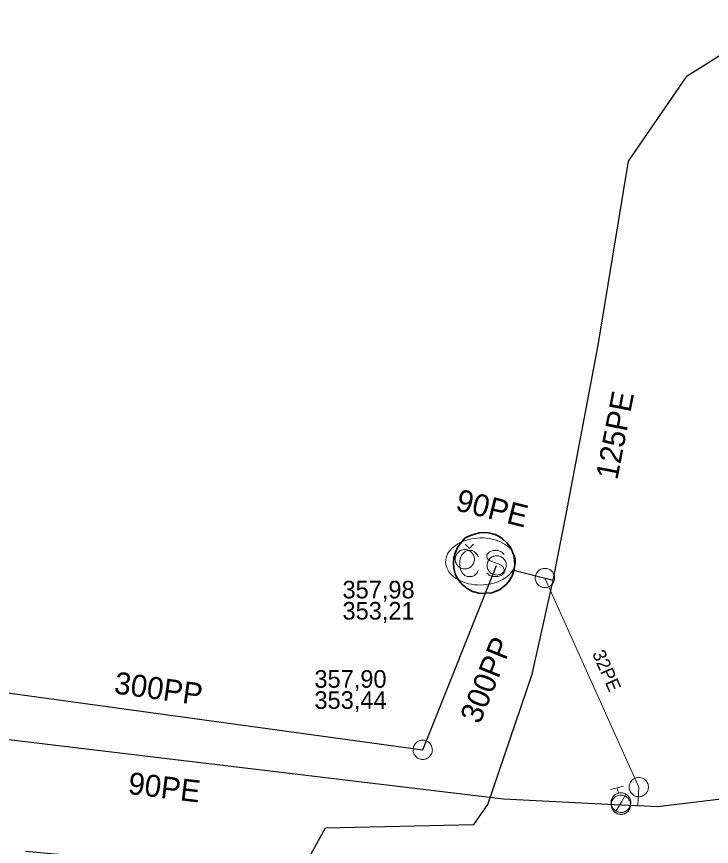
# Model space of a CAD drawing. Extents: x -741806 to -738704, y -1059275 to -1055387.
# Drawn here: x -740753.77 to -740722.25, y -1057687.05 to -1057649.38 of the extents above; entities that cross this region are included whole.
import ezdxf

# ---------------------------------------------------------------- set-up
doc = ezdxf.new("R2010")
doc.units = 0
doc.header["$LTSCALE"] = 0.4
for name, color, linetype, lineweight in [('11', 7, 'Continuous', 13), ('2', 7, 'Continuous', 25), ('21', 7, 'Continuous', 13), ('3', 7, 'Continuous', 13), ('45', 7, 'Continuous', 35), ('50', 7, 'Continuous', 13), ('51', 7, 'Continuous', 13), ('52', 7, 'Continuous', 25), ('6', 7, 'Continuous', 13)]:
    doc.layers.add(name, color=color, linetype=linetype, lineweight=lineweight)
for name, color, linetype in [('5', 7, 'Continuous'), ('53', 7, 'Continuous'), ('54', 7, 'Continuous')]:
    doc.layers.add(name, color=color, linetype=linetype)

msp = doc.modelspace()

# ---------------------------------------------------------------- linework, layer by layer
at = {"layer": '11'}
for q in [(-740733.428, -1057673.337), (-740733.036, -1057673.337)]:
    msp.add_line((-740733.232, -1057673.528), q, dxfattribs=at)
msp.add_lwpolyline([(-740731.135, -1057674.086), (-740731.143, -1057673.993), (-740731.163, -1057673.901), (-740731.194, -1057673.811), (-740731.237, -1057673.723), (-740731.292, -1057673.639), (-740731.357, -1057673.557), (-740731.432, -1057673.48), (-740731.517, -1057673.408), (-740731.612, -1057673.341), (-740731.714, -1057673.28), (-740731.824, -1057673.226), (-740731.941, -1057673.178), (-740732.064, -1057673.137), (-740732.192, -1057673.103), (-740732.324, -1057673.077), (-740732.459, -1057673.059), (-740732.596, -1057673.049), (-740732.734, -1057673.048), (-740732.872, -1057673.054), (-740733.009, -1057673.068), (-740733.143, -1057673.09), (-740733.274, -1057673.12), (-740733.402, -1057673.157), (-740733.524, -1057673.202), (-740733.64, -1057673.253), (-740733.749, -1057673.311), (-740733.85, -1057673.375), (-740733.943, -1057673.445), (-740734.027, -1057673.52), (-740734.1, -1057673.599), (-740734.164, -1057673.682), (-740734.216, -1057673.769), (-740734.257, -1057673.858), (-740734.287, -1057673.949), (-740734.305, -1057674.041), (-740734.311, -1057674.134), (-740734.305, -1057674.227), (-740734.286, -1057674.318), (-740734.257, -1057674.409), (-740734.215, -1057674.497), (-740734.162, -1057674.582), (-740734.099, -1057674.664), (-740734.025, -1057674.742), (-740733.941, -1057674.814), (-740733.848, -1057674.882), (-740733.746, -1057674.944), (-740733.637, -1057674.999), (-740733.521, -1057675.048), (-740733.399, -1057675.09), (-740733.271, -1057675.125), (-740733.14, -1057675.152), (-740733.005, -1057675.171), (-740732.868, -1057675.182), (-740732.731, -1057675.185), (-740732.593, -1057675.18), (-740732.456, -1057675.167), (-740732.321, -1057675.146), (-740732.189, -1057675.117), (-740732.061, -1057675.08), (-740731.938, -1057675.037), (-740731.822, -1057674.986), (-740731.711, -1057674.929), (-740731.609, -1057674.866), (-740731.515, -1057674.797), (-740731.43, -1057674.723), (-740731.355, -1057674.644), (-740731.29, -1057674.561), (-740731.236, -1057674.475), (-740731.193, -1057674.387), (-740731.162, -1057674.296), (-740731.143, -1057674.204), (-740731.135, -1057674.111)], close=True, dxfattribs=at)
for points in [[(-740732.828, -1057673.906), (-740732.884, -1057673.794), (-740732.996, -1057673.682), (-740733.108, -1057673.626), (-740733.33, -1057673.626), (-740733.439, -1057673.682), (-740733.551, -1057673.794), (-740733.615, -1057673.906), (-740733.671, -1057674.068), (-740733.671, -1057674.357), (-740733.615, -1057674.522), (-740733.551, -1057674.634), (-740733.439, -1057674.749), (-740733.33, -1057674.799), (-740733.108, -1057674.799), (-740732.996, -1057674.749), (-740732.884, -1057674.634), (-740732.828, -1057674.522)], [(-740731.655, -1057673.794), (-740731.767, -1057673.682), (-740731.932, -1057673.626), (-740732.156, -1057673.626), (-740732.324, -1057673.682), (-740732.442, -1057673.794), (-740732.442, -1057673.906), (-740732.389, -1057674.015), (-740732.324, -1057674.068), (-740732.21, -1057674.124), (-740731.876, -1057674.236), (-740731.767, -1057674.301), (-740731.711, -1057674.357), (-740731.655, -1057674.469), (-740731.655, -1057674.634), (-740731.767, -1057674.749), (-740731.932, -1057674.799), (-740732.156, -1057674.799), (-740732.324, -1057674.749), (-740732.442, -1057674.634)]]:
    msp.add_lwpolyline(points, dxfattribs=at)
at = {"layer": '2'}
for p, q in [((-740735.349, -1057682.666), (-740731.993, -1057674.294)), ((-740731.17, -1057674.524), (-740729.436, -1057674.959))]:
    msp.add_line(p, q, dxfattribs=at)
for points in [[(-740723.35, -1057652.071), (-740715.67, -1057647.25), (-740702.59, -1057629.575)], [(-740765.321, -1057634.66), (-740765.339, -1057637.145), (-740765.221, -1057649.531), (-740765.019, -1057662.11), (-740765.083, -1057671.477), (-740757.826, -1057679.575), (-740735.349, -1057682.666)], [(-740753.366, -1057687.272), (-740740.964, -1057688.405), (-740739.761, -1057686.21), (-740733.024, -1057686.05), (-740732.395, -1057685.151), (-740730.385, -1057679.235), (-740729.436, -1057674.959), (-740728.829, -1057671.892), (-740727.385, -1057664.297), (-740726.006, -1057655.95), (-740723.35, -1057652.071)]]:
    msp.add_lwpolyline(points, dxfattribs=at)
at = {"layer": '21'}
msp.add_lwpolyline([(-740725.581, -1057685.195), (-740725.546, -1057684.358), (-740729.804, -1057674.867)], dxfattribs=at)
at = {"layer": '3'}
for points in [[(-740732.999, -1057674.015), (-740733.002, -1057673.97), (-740733.009, -1057673.925), (-740733.021, -1057673.88), (-740733.037, -1057673.838), (-740733.058, -1057673.797), (-740733.083, -1057673.758), (-740733.112, -1057673.723), (-740733.144, -1057673.69), (-740733.18, -1057673.662), (-740733.218, -1057673.637), (-740733.259, -1057673.616), (-740733.302, -1057673.599), (-740733.346, -1057673.588), (-740733.391, -1057673.58), (-740733.437, -1057673.578), (-740733.483, -1057673.58), (-740733.528, -1057673.588), (-740733.572, -1057673.599), (-740733.615, -1057673.616), (-740733.656, -1057673.637), (-740733.694, -1057673.662), (-740733.729, -1057673.69), (-740733.762, -1057673.723), (-740733.791, -1057673.758), (-740733.816, -1057673.797), (-740733.836, -1057673.838), (-740733.853, -1057673.88), (-740733.865, -1057673.925), (-740733.872, -1057673.97), (-740733.874, -1057674.016), (-740733.872, -1057674.061), (-740733.865, -1057674.106), (-740733.853, -1057674.151), (-740733.836, -1057674.194), (-740733.816, -1057674.234), (-740733.791, -1057674.273), (-740733.762, -1057674.308), (-740733.729, -1057674.341), (-740733.694, -1057674.369), (-740733.656, -1057674.394), (-740733.615, -1057674.415), (-740733.572, -1057674.432), (-740733.528, -1057674.444), (-740733.483, -1057674.451), (-740733.437, -1057674.453), (-740733.391, -1057674.451), (-740733.346, -1057674.444), (-740733.302, -1057674.432), (-740733.259, -1057674.415), (-740733.218, -1057674.394), (-740733.18, -1057674.369), (-740733.144, -1057674.341), (-740733.112, -1057674.308), (-740733.083, -1057674.273), (-740733.058, -1057674.234), (-740733.037, -1057674.193), (-740733.021, -1057674.151), (-740733.009, -1057674.106), (-740733.002, -1057674.061), (-740732.999, -1057674.016)], [(-740731.829, -1057673.887), (-740731.872, -1057673.873), (-740731.916, -1057673.863), (-740731.963, -1057673.857), (-740732.007, -1057673.857), (-740732.053, -1057673.861), (-740732.099, -1057673.869), (-740732.142, -1057673.883), (-740732.185, -1057673.901), (-740732.224, -1057673.924), (-740732.261, -1057673.95), (-740732.296, -1057673.98), (-740732.328, -1057674.014), (-740732.355, -1057674.05), (-740732.379, -1057674.089), (-740732.398, -1057674.131), (-740732.413, -1057674.175), (-740732.422, -1057674.219), (-740732.428, -1057674.264), (-740732.429, -1057674.31), (-740732.424, -1057674.356), (-740732.415, -1057674.401), (-740732.402, -1057674.444), (-740732.384, -1057674.487), (-740732.362, -1057674.527), (-740732.335, -1057674.564), (-740732.305, -1057674.598), (-740732.272, -1057674.63), (-740732.235, -1057674.657), (-740732.196, -1057674.681), (-740732.154, -1057674.7), (-740732.111, -1057674.715), (-740732.067, -1057674.725), (-740732.021, -1057674.73), (-740731.974, -1057674.731), (-740731.93, -1057674.727), (-740731.884, -1057674.718), (-740731.841, -1057674.704), (-740731.798, -1057674.686), (-740731.759, -1057674.664), (-740731.722, -1057674.638), (-740731.687, -1057674.608), (-740731.655, -1057674.574), (-740731.628, -1057674.538), (-740731.604, -1057674.499), (-740731.585, -1057674.457), (-740731.57, -1057674.413), (-740731.56, -1057674.369), (-740731.555, -1057674.324), (-740731.555, -1057674.277), (-740731.559, -1057674.231), (-740731.568, -1057674.187), (-740731.58, -1057674.143), (-740731.599, -1057674.101), (-740731.621, -1057674.061), (-740731.648, -1057674.023), (-740731.678, -1057673.989), (-740731.711, -1057673.958), (-740731.748, -1057673.93), (-740731.787, -1057673.907), (-740731.828, -1057673.888)], [(-740734.915, -1057682.726), (-740734.911, -1057682.681), (-740734.912, -1057682.635), (-740734.918, -1057682.589), (-740734.928, -1057682.545), (-740734.943, -1057682.502), (-740734.963, -1057682.46), (-740734.987, -1057682.421), (-740735.014, -1057682.384), (-740735.046, -1057682.351), (-740735.08, -1057682.321), (-740735.118, -1057682.295), (-740735.158, -1057682.272), (-740735.2, -1057682.255), (-740735.244, -1057682.241), (-740735.289, -1057682.233), (-740735.335, -1057682.229), (-740735.381, -1057682.231), (-740735.426, -1057682.235), (-740735.471, -1057682.246), (-740735.514, -1057682.262), (-740735.555, -1057682.281), (-740735.594, -1057682.304), (-740735.631, -1057682.332), (-740735.664, -1057682.363), (-740735.694, -1057682.398), (-740735.72, -1057682.436), (-740735.742, -1057682.476), (-740735.76, -1057682.519), (-740735.773, -1057682.562), (-740735.782, -1057682.607), (-740735.786, -1057682.652), (-740735.785, -1057682.698), (-740735.779, -1057682.744), (-740735.768, -1057682.789), (-740735.754, -1057682.831), (-740735.734, -1057682.873), (-740735.71, -1057682.912), (-740735.682, -1057682.949), (-740735.651, -1057682.982), (-740735.617, -1057683.012), (-740735.579, -1057683.038), (-740735.539, -1057683.061), (-740735.497, -1057683.079), (-740735.454, -1057683.092), (-740735.408, -1057683.1), (-740735.362, -1057683.104), (-740735.317, -1057683.103), (-740735.272, -1057683.097), (-740735.227, -1057683.087), (-740735.183, -1057683.071), (-740735.142, -1057683.052), (-740735.103, -1057683.029), (-740735.067, -1057683.001), (-740735.033, -1057682.97), (-740735.003, -1057682.935), (-740734.977, -1057682.897), (-740734.955, -1057682.857), (-740734.937, -1057682.814), (-740734.924, -1057682.771), (-740734.915, -1057682.727)]]:
    msp.add_lwpolyline(points, dxfattribs=at)
at = {"layer": '45'}
msp.add_lwpolyline([(-740732.061, -1057672.894), (-740732.367, -1057672.814), (-740732.586, -1057672.8), (-740732.78, -1057672.817), (-740733.175, -1057672.941), (-740733.416, -1057673.037), (-740733.584, -1057673.244), (-740733.747, -1057673.456), (-740733.867, -1057673.695), (-740733.934, -1057673.929), (-740733.958, -1057674.171), (-740733.934, -1057674.438), (-740733.869, -1057674.673), (-740733.81, -1057674.807), (-740733.668, -1057675.034), (-740733.556, -1057675.163), (-740733.331, -1057675.348), (-740733.094, -1057675.474), (-740732.741, -1057675.568), (-740732.496, -1057675.55), (-740732.209, -1057675.535), (-740731.871, -1057675.398), (-740731.562, -1057675.161), (-740731.408, -1057674.973), (-740731.288, -1057674.761), (-740731.206, -1057674.531), (-740731.168, -1057674.272), (-740731.202, -1057673.884), (-740731.286, -1057673.63), (-740731.391, -1057673.438), (-740731.524, -1057673.264), (-740731.721, -1057673.082), (-740731.885, -1057672.976)], close=True, dxfattribs=at)
at = {"layer": '50'}
for p, q in [((-740726.231, -1057684.309), (-740726.528, -1057684.387)), ((-740726.826, -1057684.464), (-740726.528, -1057684.387)), ((-740726.465, -1057684.629), (-740726.528, -1057684.387)), ((-740726.351, -1057685.062), (-740726.125, -1057684.681)), ((-740726.351, -1057685.062), (-740726.578, -1057685.448))]:
    msp.add_line(p, q, dxfattribs=at)
msp.add_lwpolyline([(-740725.921, -1057684.954), (-740725.936, -1057684.907), (-740725.952, -1057684.864), (-740725.976, -1057684.823), (-740726.004, -1057684.786), (-740726.032, -1057684.752), (-740726.069, -1057684.719), (-740726.105, -1057684.692), (-740726.146, -1057684.667), (-740726.188, -1057684.646), (-740726.232, -1057684.633), (-740726.278, -1057684.622), (-740726.324, -1057684.615), (-740726.371, -1057684.616), (-740726.418, -1057684.62), (-740726.463, -1057684.629), (-740726.507, -1057684.643), (-740726.549, -1057684.66), (-740726.59, -1057684.684), (-740726.628, -1057684.711), (-740726.665, -1057684.742), (-740726.695, -1057684.776), (-740726.724, -1057684.814), (-740726.747, -1057684.854), (-740726.767, -1057684.895), (-740726.783, -1057684.94), (-740726.794, -1057684.986), (-740726.798, -1057685.031), (-740726.8, -1057685.079), (-740726.794, -1057685.125), (-740726.788, -1057685.171), (-740726.773, -1057685.217), (-740726.754, -1057685.259), (-740726.732, -1057685.298), (-740726.705, -1057685.339), (-740726.674, -1057685.373), (-740726.64, -1057685.406), (-740726.602, -1057685.432), (-740726.563, -1057685.458), (-740726.518, -1057685.477), (-740726.475, -1057685.491), (-740726.428, -1057685.501), (-740726.383, -1057685.506), (-740726.338, -1057685.509), (-740726.288, -1057685.504), (-740726.243, -1057685.495), (-740726.199, -1057685.481), (-740726.157, -1057685.462), (-740726.115, -1057685.44), (-740726.077, -1057685.413), (-740726.041, -1057685.381), (-740726.01, -1057685.348), (-740725.981, -1057685.31), (-740725.958, -1057685.271), (-740725.938, -1057685.229), (-740725.925, -1057685.184), (-740725.912, -1057685.139), (-740725.907, -1057685.092), (-740725.908, -1057685.046), (-740725.912, -1057684.999)], close=True, dxfattribs=at)
at = {"layer": '51'}
for points in [[(-740729.982, -1057674.468), (-740730.022, -1057674.488), (-740730.06, -1057674.513), (-740730.096, -1057674.542), (-740730.128, -1057674.574), (-740730.157, -1057674.61), (-740730.182, -1057674.648), (-740730.202, -1057674.689), (-740730.219, -1057674.732), (-740730.23, -1057674.776), (-740730.238, -1057674.821), (-740730.24, -1057674.867), (-740730.238, -1057674.913), (-740730.231, -1057674.958), (-740730.219, -1057675.002), (-740730.202, -1057675.045), (-740730.181, -1057675.086), (-740730.156, -1057675.124), (-740730.127, -1057675.16), (-740730.094, -1057675.192), (-740730.058, -1057675.221), (-740730.02, -1057675.245), (-740729.98, -1057675.267), (-740729.936, -1057675.282), (-740729.893, -1057675.294), (-740729.847, -1057675.301), (-740729.801, -1057675.304), (-740729.756, -1057675.301), (-740729.71, -1057675.294), (-740729.666, -1057675.282), (-740729.623, -1057675.266), (-740729.583, -1057675.244), (-740729.545, -1057675.22), (-740729.509, -1057675.19), (-740729.477, -1057675.158), (-740729.448, -1057675.122), (-740729.423, -1057675.084), (-740729.403, -1057675.043), (-740729.386, -1057675), (-740729.375, -1057674.956), (-740729.368, -1057674.911), (-740729.365, -1057674.865), (-740729.367, -1057674.819), (-740729.375, -1057674.774), (-740729.386, -1057674.73), (-740729.403, -1057674.687), (-740729.424, -1057674.646), (-740729.45, -1057674.608), (-740729.478, -1057674.572), (-740729.511, -1057674.54), (-740729.547, -1057674.511), (-740729.585, -1057674.487), (-740729.625, -1057674.466), (-740729.669, -1057674.45), (-740729.713, -1057674.438), (-740729.758, -1057674.431), (-740729.804, -1057674.428), (-740729.849, -1057674.431), (-740729.895, -1057674.439), (-740729.939, -1057674.451), (-740729.981, -1057674.467)], [(-740725.527, -1057683.921), (-740725.572, -1057683.921), (-740725.617, -1057683.926), (-740725.663, -1057683.936), (-740725.705, -1057683.951), (-740725.747, -1057683.97), (-740725.787, -1057683.993), (-740725.823, -1057684.021), (-740725.858, -1057684.051), (-740725.887, -1057684.086), (-740725.914, -1057684.123), (-740725.936, -1057684.163), (-740725.955, -1057684.205), (-740725.969, -1057684.249), (-740725.978, -1057684.294), (-740725.982, -1057684.339), (-740725.982, -1057684.386), (-740725.976, -1057684.431), (-740725.966, -1057684.475), (-740725.951, -1057684.519), (-740725.932, -1057684.561), (-740725.908, -1057684.6), (-740725.882, -1057684.637), (-740725.85, -1057684.67), (-740725.816, -1057684.701), (-740725.778, -1057684.727), (-740725.738, -1057684.75), (-740725.697, -1057684.768), (-740725.653, -1057684.781), (-740725.608, -1057684.79), (-740725.562, -1057684.795), (-740725.517, -1057684.794), (-740725.472, -1057684.789), (-740725.426, -1057684.779), (-740725.384, -1057684.765), (-740725.342, -1057684.745), (-740725.302, -1057684.722), (-740725.266, -1057684.694), (-740725.231, -1057684.664), (-740725.202, -1057684.629), (-740725.175, -1057684.592), (-740725.153, -1057684.552), (-740725.134, -1057684.51), (-740725.121, -1057684.466), (-740725.111, -1057684.421), (-740725.107, -1057684.376), (-740725.107, -1057684.33), (-740725.114, -1057684.284), (-740725.123, -1057684.24), (-740725.138, -1057684.196), (-740725.157, -1057684.154), (-740725.181, -1057684.115), (-740725.207, -1057684.078), (-740725.239, -1057684.045), (-740725.273, -1057684.014), (-740725.311, -1057683.988), (-740725.351, -1057683.965), (-740725.392, -1057683.947), (-740725.436, -1057683.934), (-740725.481, -1057683.925), (-740725.526, -1057683.921)], [(-740725.92, -1057685.18), (-740725.92, -1057685.135), (-740725.925, -1057685.09), (-740725.934, -1057685.044), (-740725.948, -1057685.002), (-740725.967, -1057684.96), (-740725.99, -1057684.919), (-740726.017, -1057684.883), (-740726.047, -1057684.848), (-740726.082, -1057684.819), (-740726.119, -1057684.792), (-740726.158, -1057684.769), (-740726.201, -1057684.749), (-740726.244, -1057684.735), (-740726.288, -1057684.726), (-740726.334, -1057684.722), (-740726.38, -1057684.721), (-740726.426, -1057684.726), (-740726.47, -1057684.736), (-740726.514, -1057684.75), (-740726.556, -1057684.769), (-740726.595, -1057684.792), (-740726.633, -1057684.819), (-740726.666, -1057684.85), (-740726.697, -1057684.883), (-740726.724, -1057684.921), (-740726.747, -1057684.961), (-740726.765, -1057685.002), (-740726.779, -1057685.046), (-740726.789, -1057685.091), (-740726.794, -1057685.137), (-740726.793, -1057685.182), (-740726.789, -1057685.227), (-740726.779, -1057685.273), (-740726.765, -1057685.315), (-740726.746, -1057685.357), (-740726.723, -1057685.398), (-740726.696, -1057685.434), (-740726.666, -1057685.469), (-740726.631, -1057685.498), (-740726.595, -1057685.525), (-740726.555, -1057685.548), (-740726.513, -1057685.568), (-740726.469, -1057685.581), (-740726.425, -1057685.591), (-740726.379, -1057685.595), (-740726.333, -1057685.596), (-740726.287, -1057685.59), (-740726.243, -1057685.581), (-740726.199, -1057685.567), (-740726.157, -1057685.548), (-740726.118, -1057685.525), (-740726.08, -1057685.498), (-740726.047, -1057685.467), (-740726.016, -1057685.434), (-740725.989, -1057685.396), (-740725.966, -1057685.356), (-740725.948, -1057685.315), (-740725.934, -1057685.271), (-740725.924, -1057685.226), (-740725.92, -1057685.181)]]:
    msp.add_lwpolyline(points, dxfattribs=at)
at = {"layer": '52'}
msp.add_line((-740726.357, -1057685.158), (-740726.353, -1057685.058), dxfattribs=at)
msp.add_lwpolyline([(-740767.701, -1057643.739), (-740767.68, -1057653.215), (-740767.688, -1057656.303), (-740767.625, -1057659.884), (-740767.56, -1057663.571), (-740767.412, -1057673.085), (-740759.954, -1057681.499), (-740731.682, -1057684.887), (-740726.357, -1057685.158), (-740725.284, -1057685.21), (-740724.688, -1057685.239), (-740698.842, -1057682.125), (-740692.883, -1057686.829)], dxfattribs=at)

# ---------------------------------------------------------------- texts
at = {"layer": '5'}
for s, rotation, p in [('125PE ', 79, (-740726.521, -1057670.451)), ('90PE', 346, (-740733.9, -1057671.784)), ('300PP ', 68, (-740732.758, -1057681.538)), ('300PP ', 352, (-740749.386, -1057680.1))]:
    msp.add_text(s, height=1, rotation=rotation, dxfattribs=at).set_placement(p)
at = {"layer": '53'}
msp.add_text('90PE', height=1, rotation=353, dxfattribs=at).set_placement((-740748.751, -1057684.662))
at = {"layer": '54'}
msp.add_text('32PE', height=0.6, rotation=294, dxfattribs=at).set_placement((-740727.672, -1057678.295))
at = {"layer": '6'}
for s, p in [('357,98', (-740738.987, -1057675.794)), ('353,21', (-740738.987, -1057676.754)), ('357,90', (-740740.26, -1057679.848)), ('353,44', (-740740.26, -1057680.808))]:
    msp.add_text(s, height=0.8, dxfattribs=at).set_placement(p)

doc.saveas('drawing.dxf')
